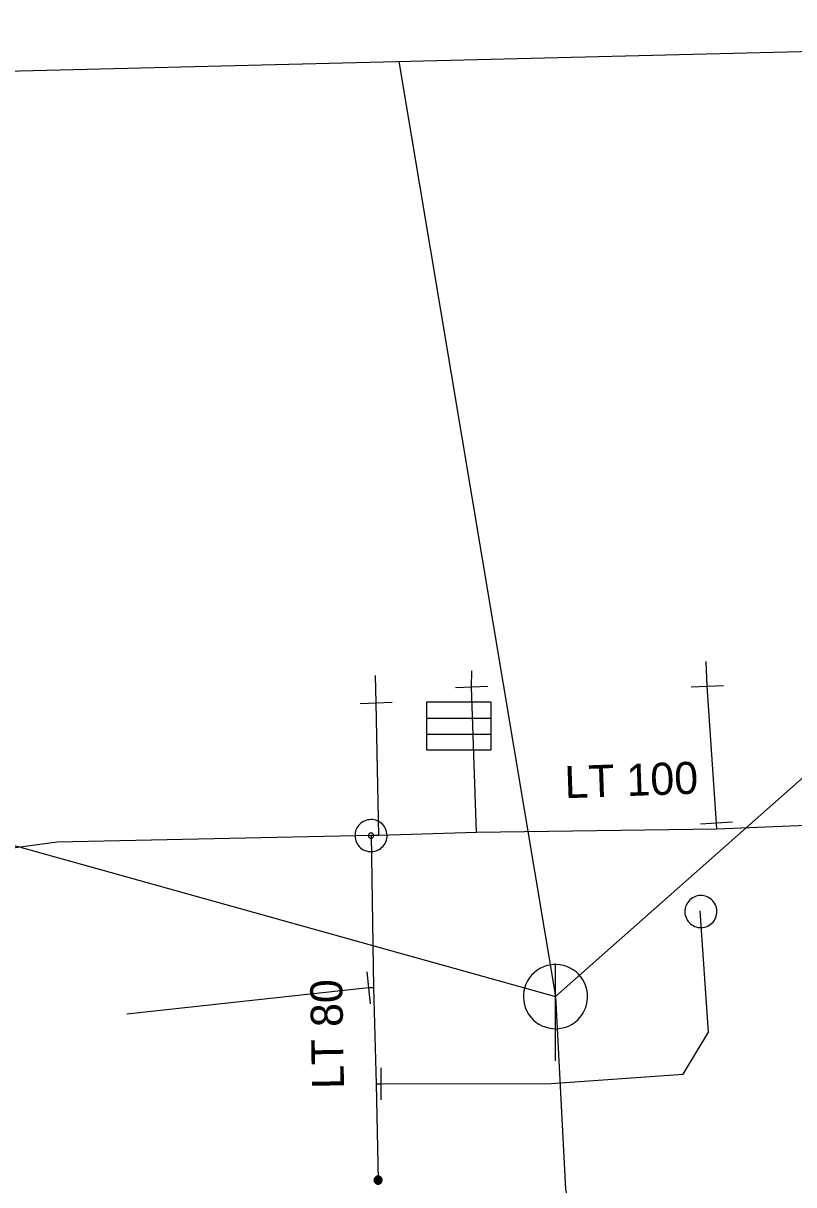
# Model space of a CAD drawing. Extents: x -725807 to -725723.1, y -978165.9 to -978101.2.
# Drawn here: x -725783 to -725758.99, y -978137.33 to -978101.16 of the extents above; entities that cross this region are included whole.
import ezdxf

# ---------------------------------------------------------------- set-up
doc = ezdxf.new("R2010")
doc.units = 0
for name, color, linetype in [('Vrstva 1', 7, 'Continuous'), ('Vrstva 13', 7, 'Continuous'), ('Vrstva 14', 7, 'Continuous'), ('Vrstva 17', 7, 'Continuous'), ('Vrstva 22', 7, 'Continuous'), ('Vrstva 23', 7, 'Continuous'), ('Vrstva 34', 7, 'Continuous'), ('Vrstva 47', 7, 'Continuous'), ('Vrstva 9', 7, 'Continuous')]:
    doc.layers.add(name, color=color, linetype=linetype)

msp = doc.modelspace()

# ---------------------------------------------------------------- linework, layer by layer
at = {"layer": 'Vrstva 1'}
msp.add_lwpolyline([(-725807.01, -978138.838), (-725796.543, -978102.971), (-725723.134, -978101.157), (-725729.135, -978159.354), (-725758.583, -978165.913), (-725792.915, -978158.237)], close=True, dxfattribs=at)
at = {"layer": 'Vrstva 13'}
for points in [[(-725761.689, -978121.798), (-725761.728, -978121.035)], [(-725772.006, -978122.318), (-725772.024, -978121.471)], [(-725769.031, -978121.822), (-725769.026, -978121.326)], [(-725768.881, -978126.353), (-725769.031, -978121.822)], [(-725761.4, -978126.068), (-725761.689, -978121.798)], [(-725771.927, -978126.449), (-725772.006, -978122.318)], [(-725771.861, -978134.181), (-725766.555, -978134.175), (-725762.44, -978133.877), (-725761.649, -978132.576), (-725761.907, -978128.792)], [(-725772.245, -978131.191), (-725779.778, -978132.017)]]:
    msp.add_lwpolyline(points, dxfattribs=at)
at = {"layer": 'Vrstva 14'}
for points in [[(-725771.298, -978102.347), (-725766.42, -978131.467)], [(-725801.965, -978121.55), (-725766.42, -978131.467)], [(-725750.922, -978123.543), (-725758.582, -978124.535), (-725766.42, -978131.467)], [(-725761.388, -978126.258), (-725761.4, -978126.068)], [(-725772.085, -978131.19), (-725772.245, -978131.191)], [(-725766.42, -978131.467), (-725766.103, -978137.458), (-725764.695, -978144.424), (-725761.772, -978159.113), (-725761.702, -978159.462), (-725760.504, -978165.484)], [(-725772.01, -978134.181), (-725771.861, -978134.181)]]:
    msp.add_lwpolyline(points, dxfattribs=at)
at = {"layer": 'Vrstva 17'}
for points in [[(-725754.02, -978125.954), (-725761.388, -978126.258), (-725768.881, -978126.353), (-725771.927, -978126.449), (-725772.166, -978126.454)], [(-725772.166, -978126.454), (-725781.945, -978126.655), (-725795.783, -978128.538)], [(-725772.166, -978126.454), (-725772.085, -978131.19), (-725772.01, -978134.181), (-725771.946, -978137.181)]]:
    msp.add_lwpolyline(points, dxfattribs=at)
at = {"layer": 'Vrstva 22'}
for points in [[(-725770.431, -978122.293), (-725768.431, -978122.293), (-725768.431, -978123.793), (-725770.431, -978123.793), (-725770.431, -978122.293)], [(-725770.431, -978122.793), (-725768.431, -978122.793)], [(-725770.431, -978123.293), (-725768.431, -978123.293)], [(-725765.42, -978131.467), (-725765.425, -978131.358), (-725765.443, -978131.25), (-725765.473, -978131.144), (-725765.513, -978131.043), (-725765.565, -978130.946), (-725765.627, -978130.856), (-725765.699, -978130.773), (-725765.779, -978130.699), (-725765.867, -978130.633), (-725765.961, -978130.578), (-725766.061, -978130.533), (-725766.166, -978130.5), (-725766.273, -978130.478), (-725766.382, -978130.468), (-725766.492, -978130.47), (-725766.6, -978130.484), (-725766.707, -978130.509), (-725766.81, -978130.546), (-725766.908, -978130.595), (-725767, -978130.653), (-725767.086, -978130.722), (-725767.163, -978130.799), (-725767.232, -978130.885), (-725767.291, -978130.977), (-725767.339, -978131.075), (-725767.376, -978131.178), (-725767.402, -978131.285), (-725767.416, -978131.393), (-725767.419, -978131.503), (-725767.409, -978131.612), (-725767.388, -978131.719), (-725767.354, -978131.823), (-725767.31, -978131.923), (-725767.255, -978132.018), (-725767.189, -978132.106), (-725767.115, -978132.186), (-725767.032, -978132.258), (-725766.942, -978132.32), (-725766.846, -978132.372), (-725766.744, -978132.413), (-725766.639, -978132.443), (-725766.531, -978132.461), (-725766.421, -978132.467), (-725766.312, -978132.461), (-725766.204, -978132.443), (-725766.099, -978132.414), (-725765.997, -978132.373), (-725765.9, -978132.321), (-725765.81, -978132.259), (-725765.727, -978132.188), (-725765.652, -978132.108), (-725765.587, -978132.02), (-725765.531, -978131.926), (-725765.487, -978131.826), (-725765.453, -978131.722), (-725765.431, -978131.614), (-725765.421, -978131.505), (-725765.42, -978131.467)], [(-725766.42, -978133.467), (-725766.419, -978130.467)]]:
    msp.add_lwpolyline(points, dxfattribs=at)
at = {"layer": 'Vrstva 23'}
for points in [[(-725762.148, -978128.392), (-725762.191, -978128.422)], [(-725762.148, -978128.392), (-725762.191, -978128.422)], [(-725762.103, -978128.368), (-725762.148, -978128.392)], [(-725762.103, -978128.368), (-725762.148, -978128.392)], [(-725762.054, -978128.347), (-725762.103, -978128.368)], [(-725762.054, -978128.347), (-725762.103, -978128.368)], [(-725762.004, -978128.332), (-725762.054, -978128.347)], [(-725762.004, -978128.332), (-725762.054, -978128.347)], [(-725761.952, -978128.323), (-725762.004, -978128.332)], [(-725761.952, -978128.323), (-725762.004, -978128.332)], [(-725761.901, -978128.318), (-725761.952, -978128.323)], [(-725761.901, -978128.318), (-725761.952, -978128.323)], [(-725761.848, -978128.32), (-725761.901, -978128.318)], [(-725761.848, -978128.32), (-725761.901, -978128.318)], [(-725761.796, -978128.327), (-725761.848, -978128.32)], [(-725761.796, -978128.327), (-725761.848, -978128.32)], [(-725761.745, -978128.34), (-725761.796, -978128.327)], [(-725761.745, -978128.34), (-725761.796, -978128.327)], [(-725761.697, -978128.358), (-725761.745, -978128.34)], [(-725761.697, -978128.358), (-725761.745, -978128.34)], [(-725761.649, -978128.38), (-725761.697, -978128.358)], [(-725761.649, -978128.38), (-725761.697, -978128.358)], [(-725761.605, -978128.407), (-725761.649, -978128.38)], [(-725761.605, -978128.407), (-725761.649, -978128.38)], [(-725762.38, -978128.725), (-725762.387, -978128.779)], [(-725762.38, -978128.725), (-725762.387, -978128.779)], [(-725762.367, -978128.675), (-725762.38, -978128.725)], [(-725762.367, -978128.675), (-725762.38, -978128.725)], [(-725762.35, -978128.626), (-725762.367, -978128.675)], [(-725762.35, -978128.626), (-725762.367, -978128.675)], [(-725762.328, -978128.58), (-725762.35, -978128.626)], [(-725762.328, -978128.58), (-725762.35, -978128.626)], [(-725762.3, -978128.534), (-725762.328, -978128.58)], [(-725762.3, -978128.534), (-725762.328, -978128.58)], [(-725762.267, -978128.493), (-725762.3, -978128.534)], [(-725762.267, -978128.493), (-725762.3, -978128.534)], [(-725762.231, -978128.455), (-725762.267, -978128.493)], [(-725762.231, -978128.455), (-725762.267, -978128.493)], [(-725762.191, -978128.422), (-725762.231, -978128.455)], [(-725762.191, -978128.422), (-725762.231, -978128.455)], [(-725761.563, -978128.439), (-725761.605, -978128.407)], [(-725761.563, -978128.439), (-725761.605, -978128.407)], [(-725761.525, -978128.476), (-725761.563, -978128.439)], [(-725761.525, -978128.476), (-725761.563, -978128.439)], [(-725761.491, -978128.516), (-725761.525, -978128.476)], [(-725761.491, -978128.516), (-725761.525, -978128.476)], [(-725761.463, -978128.559), (-725761.491, -978128.516)], [(-725761.463, -978128.559), (-725761.491, -978128.516)], [(-725761.436, -978128.605), (-725761.463, -978128.559)], [(-725761.436, -978128.605), (-725761.463, -978128.559)], [(-725761.417, -978128.653), (-725761.436, -978128.605)], [(-725761.417, -978128.653), (-725761.436, -978128.605)], [(-725761.403, -978128.704), (-725761.417, -978128.653)], [(-725761.403, -978128.704), (-725761.417, -978128.653)], [(-725761.393, -978128.755), (-725761.403, -978128.704)], [(-725761.393, -978128.755), (-725761.403, -978128.704)], [(-725761.389, -978128.807), (-725761.393, -978128.755)], [(-725761.389, -978128.807), (-725761.393, -978128.755)], [(-725762.387, -978128.779), (-725762.389, -978128.83)], [(-725762.387, -978128.779), (-725762.389, -978128.83)], [(-725762.389, -978128.83), (-725762.384, -978128.884)], [(-725762.389, -978128.83), (-725762.384, -978128.884)], [(-725762.384, -978128.884), (-725762.376, -978128.933)], [(-725762.384, -978128.884), (-725762.376, -978128.933)], [(-725762.376, -978128.933), (-725762.362, -978128.984)], [(-725762.376, -978128.933), (-725762.362, -978128.984)], [(-725762.362, -978128.984), (-725762.34, -978129.033)], [(-725762.362, -978128.984), (-725762.34, -978129.033)], [(-725762.34, -978129.033), (-725762.315, -978129.079)], [(-725762.34, -978129.033), (-725762.315, -978129.079)], [(-725762.315, -978129.079), (-725762.285, -978129.123)], [(-725762.315, -978129.079), (-725762.285, -978129.123)], [(-725761.51, -978129.145), (-725761.478, -978129.103)], [(-725761.51, -978129.145), (-725761.478, -978129.103)], [(-725761.478, -978129.103), (-725761.45, -978129.059)], [(-725761.478, -978129.103), (-725761.45, -978129.059)], [(-725761.45, -978129.059), (-725761.428, -978129.011)], [(-725761.45, -978129.059), (-725761.428, -978129.011)], [(-725761.428, -978129.011), (-725761.411, -978128.962)], [(-725761.428, -978129.011), (-725761.411, -978128.962)], [(-725761.411, -978128.962), (-725761.398, -978128.912)], [(-725761.411, -978128.962), (-725761.398, -978128.912)], [(-725761.398, -978128.912), (-725761.391, -978128.86)], [(-725761.398, -978128.912), (-725761.391, -978128.86)], [(-725761.391, -978128.86), (-725761.389, -978128.807)], [(-725761.391, -978128.86), (-725761.389, -978128.807)], [(-725762.285, -978129.123), (-725762.253, -978129.163)], [(-725762.285, -978129.123), (-725762.253, -978129.163)], [(-725762.253, -978129.163), (-725762.215, -978129.198)], [(-725762.253, -978129.163), (-725762.215, -978129.198)], [(-725762.215, -978129.198), (-725762.172, -978129.23)], [(-725762.215, -978129.198), (-725762.172, -978129.23)], [(-725762.172, -978129.23), (-725762.129, -978129.257)], [(-725762.172, -978129.23), (-725762.129, -978129.257)], [(-725762.129, -978129.257), (-725762.081, -978129.28)], [(-725762.129, -978129.257), (-725762.081, -978129.28)], [(-725762.081, -978129.28), (-725762.032, -978129.297)], [(-725762.081, -978129.28), (-725762.032, -978129.297)], [(-725762.032, -978129.297), (-725761.981, -978129.31)], [(-725762.032, -978129.297), (-725761.981, -978129.31)], [(-725761.981, -978129.31), (-725761.93, -978129.317)], [(-725761.981, -978129.31), (-725761.93, -978129.317)], [(-725761.93, -978129.317), (-725761.877, -978129.319)], [(-725761.93, -978129.317), (-725761.877, -978129.319)], [(-725761.877, -978129.319), (-725761.824, -978129.315)], [(-725761.877, -978129.319), (-725761.824, -978129.315)], [(-725761.824, -978129.315), (-725761.773, -978129.306)], [(-725761.824, -978129.315), (-725761.773, -978129.306)], [(-725761.773, -978129.306), (-725761.724, -978129.29)], [(-725761.773, -978129.306), (-725761.724, -978129.29)], [(-725761.724, -978129.29), (-725761.675, -978129.27)], [(-725761.724, -978129.29), (-725761.675, -978129.27)], [(-725761.675, -978129.27), (-725761.629, -978129.246)], [(-725761.675, -978129.27), (-725761.629, -978129.246)], [(-725761.629, -978129.246), (-725761.585, -978129.216)], [(-725761.629, -978129.246), (-725761.585, -978129.216)], [(-725761.585, -978129.216), (-725761.546, -978129.182)], [(-725761.585, -978129.216), (-725761.546, -978129.182)], [(-725761.546, -978129.182), (-725761.51, -978129.145)], [(-725761.546, -978129.182), (-725761.51, -978129.145)]]:
    msp.add_lwpolyline(points, dxfattribs=at)
at = {"layer": 'Vrstva 34'}
for points in [[(-725769.53, -978121.841), (-725768.531, -978121.803)], [(-725762.188, -978121.817), (-725761.189, -978121.779)], [(-725772.505, -978122.337), (-725771.506, -978122.299)], [(-725760.901, -978126.033), (-725761.898, -978126.101)], [(-725772.299, -978130.694), (-725772.19, -978131.688)], [(-725771.858, -978133.681), (-725771.864, -978134.68)]]:
    msp.add_lwpolyline(points, dxfattribs=at)
at = {"layer": 'Vrstva 47'}
for points in [[(-725772.155, -978126.953), (-725772.103, -978126.949), (-725772.051, -978126.94), (-725772.002, -978126.925), (-725771.953, -978126.906), (-725771.907, -978126.881), (-725771.863, -978126.851), (-725771.824, -978126.818), (-725771.788, -978126.78), (-725771.756, -978126.739), (-725771.727, -978126.695), (-725771.704, -978126.647), (-725771.687, -978126.598), (-725771.674, -978126.547), (-725771.668, -978126.495), (-725771.666, -978126.443), (-725771.67, -978126.391), (-725771.679, -978126.339), (-725771.694, -978126.289), (-725771.713, -978126.241), (-725771.738, -978126.195), (-725771.768, -978126.151), (-725771.801, -978126.111), (-725771.839, -978126.075), (-725771.88, -978126.043), (-725771.924, -978126.015), (-725771.972, -978125.992), (-725772.021, -978125.974), (-725772.072, -978125.962), (-725772.124, -978125.956), (-725772.176, -978125.954), (-725772.228, -978125.958), (-725772.28, -978125.967), (-725772.33, -978125.981), (-725772.378, -978126.001), (-725772.424, -978126.026), (-725772.468, -978126.055), (-725772.508, -978126.088), (-725772.544, -978126.126), (-725772.576, -978126.168), (-725772.604, -978126.212), (-725772.627, -978126.26), (-725772.645, -978126.308), (-725772.657, -978126.36), (-725772.663, -978126.412), (-725772.665, -978126.464), (-725772.661, -978126.516), (-725772.652, -978126.568), (-725772.638, -978126.617), (-725772.618, -978126.666), (-725772.593, -978126.712), (-725772.564, -978126.756), (-725772.531, -978126.795), (-725772.493, -978126.831), (-725772.451, -978126.863), (-725772.407, -978126.892), (-725772.359, -978126.915), (-725772.311, -978126.932), (-725772.259, -978126.945), (-725772.207, -978126.951), (-725772.155, -978126.953)], [(-725772.164, -978126.535), (-725772.155, -978126.535), (-725772.147, -978126.533), (-725772.139, -978126.531), (-725772.131, -978126.528), (-725772.123, -978126.524), (-725772.116, -978126.519), (-725772.109, -978126.513), (-725772.103, -978126.507), (-725772.099, -978126.5), (-725772.094, -978126.493), (-725772.09, -978126.485), (-725772.087, -978126.477), (-725772.085, -978126.469), (-725772.083, -978126.461), (-725772.084, -978126.452), (-725772.084, -978126.443), (-725772.086, -978126.435), (-725772.088, -978126.427), (-725772.091, -978126.419), (-725772.095, -978126.411), (-725772.1, -978126.404), (-725772.106, -978126.397), (-725772.112, -978126.391), (-725772.119, -978126.386), (-725772.126, -978126.382), (-725772.134, -978126.378), (-725772.142, -978126.375), (-725772.15, -978126.373), (-725772.158, -978126.371), (-725772.167, -978126.372), (-725772.176, -978126.372), (-725772.184, -978126.374), (-725772.192, -978126.376), (-725772.2, -978126.379), (-725772.208, -978126.383), (-725772.215, -978126.387), (-725772.222, -978126.394), (-725772.228, -978126.4), (-725772.233, -978126.407), (-725772.237, -978126.414), (-725772.241, -978126.422), (-725772.244, -978126.43), (-725772.246, -978126.438), (-725772.248, -978126.446), (-725772.247, -978126.455), (-725772.247, -978126.464), (-725772.245, -978126.472), (-725772.243, -978126.48), (-725772.24, -978126.488), (-725772.236, -978126.496), (-725772.232, -978126.503), (-725772.225, -978126.51), (-725772.219, -978126.516), (-725772.212, -978126.52), (-725772.205, -978126.525), (-725772.197, -978126.529), (-725772.189, -978126.532), (-725772.181, -978126.534), (-725772.173, -978126.536), (-725772.164, -978126.535)]]:
    msp.add_lwpolyline(points, dxfattribs=at)
at = {"layer": 'Vrstva 9'}
for points in [[(-725772.072, -978137.181), (-725772.072, -978137.194), (-725772.07, -978137.207), (-725772.067, -978137.22), (-725772.062, -978137.232), (-725772.056, -978137.244), (-725772.049, -978137.255), (-725772.041, -978137.265), (-725772.031, -978137.275), (-725772.021, -978137.283), (-725772.01, -978137.29), (-725771.998, -978137.296), (-725771.986, -978137.301), (-725771.973, -978137.304), (-725771.96, -978137.306), (-725771.947, -978137.308), (-725771.934, -978137.307), (-725771.921, -978137.305), (-725771.908, -978137.302), (-725771.896, -978137.297), (-725771.884, -978137.291), (-725771.873, -978137.284), (-725771.863, -978137.276), (-725771.853, -978137.266), (-725771.845, -978137.256), (-725771.838, -978137.245), (-725771.832, -978137.233), (-725771.827, -978137.221), (-725771.824, -978137.208), (-725771.822, -978137.195), (-725771.82, -978137.182), (-725771.821, -978137.169), (-725771.823, -978137.156), (-725771.826, -978137.143), (-725771.831, -978137.131), (-725771.837, -978137.119), (-725771.844, -978137.108), (-725771.852, -978137.098), (-725771.862, -978137.088), (-725771.872, -978137.08), (-725771.883, -978137.073), (-725771.895, -978137.067), (-725771.907, -978137.062), (-725771.92, -978137.059), (-725771.933, -978137.057), (-725771.946, -978137.056), (-725771.959, -978137.056), (-725771.972, -978137.058), (-725771.985, -978137.061), (-725771.997, -978137.066), (-725772.009, -978137.072), (-725772.02, -978137.079), (-725772.03, -978137.087), (-725772.04, -978137.097), (-725772.048, -978137.107), (-725772.055, -978137.118), (-725772.061, -978137.13), (-725772.066, -978137.142), (-725772.069, -978137.155), (-725772.071, -978137.168), (-725772.072, -978137.181)], [(-725772.052, -978137.181), (-725772.053, -978137.192), (-725772.051, -978137.203), (-725772.048, -978137.214), (-725772.044, -978137.224), (-725772.039, -978137.234), (-725772.033, -978137.243), (-725772.026, -978137.252), (-725772.018, -978137.26), (-725772.009, -978137.267), (-725772, -978137.273), (-725771.99, -978137.278), (-725771.98, -978137.282), (-725771.969, -978137.285), (-725771.958, -978137.288), (-725771.947, -978137.288), (-725771.936, -978137.288), (-725771.925, -978137.286), (-725771.914, -978137.283), (-725771.904, -978137.279), (-725771.894, -978137.274), (-725771.885, -978137.268), (-725771.876, -978137.261), (-725771.868, -978137.253), (-725771.861, -978137.244), (-725771.855, -978137.235), (-725771.85, -978137.225), (-725771.846, -978137.215), (-725771.843, -978137.204), (-725771.841, -978137.193), (-725771.84, -978137.182), (-725771.84, -978137.171), (-725771.842, -978137.16), (-725771.845, -978137.149), (-725771.849, -978137.139), (-725771.854, -978137.129), (-725771.86, -978137.12), (-725771.867, -978137.111), (-725771.875, -978137.103), (-725771.884, -978137.096), (-725771.893, -978137.09), (-725771.903, -978137.085), (-725771.913, -978137.081), (-725771.924, -978137.078), (-725771.934, -978137.076), (-725771.946, -978137.076), (-725771.957, -978137.075), (-725771.968, -978137.077), (-725771.979, -978137.08), (-725771.989, -978137.084), (-725771.999, -978137.089), (-725772.008, -978137.095), (-725772.017, -978137.102), (-725772.025, -978137.11), (-725772.032, -978137.119), (-725772.038, -978137.128), (-725772.043, -978137.138), (-725772.047, -978137.148), (-725772.05, -978137.159), (-725772.052, -978137.17), (-725772.052, -978137.181)], [(-725772.033, -978137.181), (-725772.033, -978137.19), (-725772.032, -978137.199), (-725772.029, -978137.208), (-725772.026, -978137.216), (-725772.022, -978137.224), (-725772.017, -978137.232), (-725772.011, -978137.239), (-725772.005, -978137.245), (-725771.998, -978137.251), (-725771.99, -978137.256), (-725771.982, -978137.26), (-725771.974, -978137.263), (-725771.965, -978137.266), (-725771.956, -978137.267), (-725771.947, -978137.269), (-725771.938, -978137.268), (-725771.929, -978137.267), (-725771.92, -978137.264), (-725771.912, -978137.261), (-725771.904, -978137.257), (-725771.896, -978137.252), (-725771.889, -978137.246), (-725771.883, -978137.24), (-725771.877, -978137.233), (-725771.872, -978137.225), (-725771.868, -978137.217), (-725771.865, -978137.209), (-725771.862, -978137.2), (-725771.861, -978137.191), (-725771.858, -978137.182), (-725771.86, -978137.173), (-725771.861, -978137.164), (-725771.864, -978137.155), (-725771.867, -978137.147), (-725771.871, -978137.139), (-725771.876, -978137.131), (-725771.882, -978137.124), (-725771.888, -978137.118), (-725771.895, -978137.112), (-725771.903, -978137.107), (-725771.911, -978137.103), (-725771.919, -978137.1), (-725771.928, -978137.097), (-725771.937, -978137.096), (-725771.946, -978137.095), (-725771.955, -978137.095), (-725771.964, -978137.096), (-725771.973, -978137.099), (-725771.981, -978137.102), (-725771.989, -978137.106), (-725771.997, -978137.111), (-725772.004, -978137.117), (-725772.01, -978137.123), (-725772.016, -978137.13), (-725772.021, -978137.138), (-725772.025, -978137.146), (-725772.028, -978137.154), (-725772.031, -978137.163), (-725772.032, -978137.172), (-725772.033, -978137.181)], [(-725772.013, -978137.181), (-725772.013, -978137.188), (-725772.012, -978137.195), (-725772.011, -978137.202), (-725772.008, -978137.208), (-725772.005, -978137.214), (-725772.001, -978137.22), (-725771.997, -978137.226), (-725771.992, -978137.231), (-725771.986, -978137.235), (-725771.98, -978137.239), (-725771.974, -978137.242), (-725771.968, -978137.245), (-725771.961, -978137.246), (-725771.954, -978137.249), (-725771.947, -978137.249), (-725771.94, -978137.249), (-725771.933, -978137.247), (-725771.926, -978137.246), (-725771.92, -978137.243), (-725771.913, -978137.24), (-725771.908, -978137.236), (-725771.902, -978137.232), (-725771.897, -978137.227), (-725771.893, -978137.221), (-725771.889, -978137.215), (-725771.886, -978137.209), (-725771.883, -978137.203), (-725771.881, -978137.196), (-725771.88, -978137.189), (-725771.879, -978137.182), (-725771.879, -978137.175), (-725771.88, -978137.168), (-725771.882, -978137.161), (-725771.885, -978137.155), (-725771.888, -978137.148), (-725771.892, -978137.143), (-725771.896, -978137.137), (-725771.901, -978137.132), (-725771.907, -978137.128), (-725771.912, -978137.124), (-725771.919, -978137.121), (-725771.925, -978137.118), (-725771.932, -978137.116), (-725771.939, -978137.115), (-725771.946, -978137.115), (-725771.953, -978137.115), (-725771.96, -978137.115), (-725771.967, -978137.117), (-725771.973, -978137.12), (-725771.979, -978137.123), (-725771.985, -978137.127), (-725771.991, -978137.131), (-725771.996, -978137.136), (-725772, -978137.142), (-725772.004, -978137.147), (-725772.007, -978137.154), (-725772.01, -978137.16), (-725772.011, -978137.167), (-725772.013, -978137.174), (-725772.013, -978137.181)], [(-725771.993, -978137.181), (-725771.993, -978137.186), (-725771.993, -978137.191), (-725771.992, -978137.196), (-725771.99, -978137.2), (-725771.988, -978137.205), (-725771.985, -978137.209), (-725771.982, -978137.212), (-725771.978, -978137.216), (-725771.975, -978137.219), (-725771.971, -978137.222), (-725771.966, -978137.224), (-725771.962, -978137.226), (-725771.957, -978137.227), (-725771.952, -978137.229), (-725771.947, -978137.229), (-725771.942, -978137.229), (-725771.937, -978137.228), (-725771.932, -978137.227), (-725771.928, -978137.225), (-725771.923, -978137.223), (-725771.919, -978137.22), (-725771.915, -978137.217), (-725771.912, -978137.213), (-725771.909, -978137.21), (-725771.906, -978137.206), (-725771.904, -978137.201), (-725771.902, -978137.197), (-725771.901, -978137.192), (-725771.9, -978137.187), (-725771.899, -978137.182), (-725771.899, -978137.177), (-725771.9, -978137.172), (-725771.901, -978137.167), (-725771.903, -978137.163), (-725771.905, -978137.158), (-725771.908, -978137.154), (-725771.911, -978137.15), (-725771.914, -978137.147), (-725771.918, -978137.144), (-725771.922, -978137.141), (-725771.927, -978137.139), (-725771.931, -978137.137), (-725771.936, -978137.136), (-725771.941, -978137.135), (-725771.946, -978137.135), (-725771.951, -978137.135), (-725771.956, -978137.136), (-725771.961, -978137.136), (-725771.965, -978137.138), (-725771.97, -978137.14), (-725771.974, -978137.143), (-725771.977, -978137.146), (-725771.981, -978137.149), (-725771.983, -978137.153), (-725771.987, -978137.157), (-725771.989, -978137.162), (-725771.991, -978137.166), (-725771.992, -978137.171), (-725771.993, -978137.176), (-725771.993, -978137.181)], [(-725771.973, -978137.181), (-725771.973, -978137.184), (-725771.974, -978137.187), (-725771.973, -978137.189), (-725771.972, -978137.192), (-725771.971, -978137.195), (-725771.969, -978137.197), (-725771.967, -978137.199), (-725771.965, -978137.201), (-725771.963, -978137.203), (-725771.961, -978137.205), (-725771.958, -978137.207), (-725771.955, -978137.208), (-725771.953, -978137.208), (-725771.95, -978137.209), (-725771.947, -978137.209), (-725771.944, -978137.209), (-725771.941, -978137.209), (-725771.938, -978137.208), (-725771.936, -978137.207), (-725771.933, -978137.206), (-725771.931, -978137.204), (-725771.928, -978137.202), (-725771.926, -978137.2), (-725771.925, -978137.198), (-725771.923, -978137.196), (-725771.922, -978137.193), (-725771.92, -978137.19), (-725771.92, -978137.188), (-725771.919, -978137.185), (-725771.918, -978137.182), (-725771.919, -978137.179), (-725771.919, -978137.176), (-725771.92, -978137.173), (-725771.921, -978137.171), (-725771.922, -978137.168), (-725771.924, -978137.166), (-725771.925, -978137.163), (-725771.927, -978137.161), (-725771.93, -978137.16), (-725771.932, -978137.158), (-725771.934, -978137.157), (-725771.937, -978137.156), (-725771.94, -978137.155), (-725771.943, -978137.155), (-725771.946, -978137.154), (-725771.949, -978137.155), (-725771.952, -978137.154), (-725771.954, -978137.156), (-725771.957, -978137.156), (-725771.96, -978137.157), (-725771.962, -978137.159), (-725771.964, -978137.16), (-725771.966, -978137.162), (-725771.968, -978137.165), (-725771.97, -978137.167), (-725771.971, -978137.17), (-725771.972, -978137.172), (-725771.973, -978137.175), (-725771.973, -978137.178), (-725771.973, -978137.181)], [(-725771.954, -978137.181), (-725771.954, -978137.183), (-725771.954, -978137.183), (-725771.953, -978137.183), (-725771.953, -978137.185), (-725771.954, -978137.186), (-725771.952, -978137.186), (-725771.952, -978137.186), (-725771.952, -978137.188), (-725771.952, -978137.188), (-725771.951, -978137.189), (-725771.949, -978137.189), (-725771.949, -978137.189), (-725771.949, -978137.19), (-725771.947, -978137.19), (-725771.947, -978137.19), (-725771.946, -978137.19), (-725771.945, -978137.19), (-725771.945, -978137.189), (-725771.944, -978137.189), (-725771.942, -978137.189), (-725771.942, -978137.188), (-725771.942, -978137.188), (-725771.941, -978137.187), (-725771.941, -978137.187), (-725771.939, -978137.186), (-725771.939, -978137.185), (-725771.938, -978137.184), (-725771.938, -978137.184), (-725771.938, -978137.183), (-725771.938, -978137.182), (-725771.938, -978137.181), (-725771.938, -978137.18), (-725771.938, -978137.18), (-725771.939, -978137.179), (-725771.939, -978137.178), (-725771.94, -978137.177), (-725771.94, -978137.177), (-725771.941, -978137.176), (-725771.941, -978137.176), (-725771.942, -978137.175), (-725771.943, -978137.175), (-725771.944, -978137.174), (-725771.944, -978137.174), (-725771.945, -978137.174), (-725771.946, -978137.174), (-725771.947, -978137.174), (-725771.948, -978137.174), (-725771.948, -978137.174), (-725771.949, -978137.175), (-725771.95, -978137.174), (-725771.951, -978137.176), (-725771.951, -978137.176), (-725771.952, -978137.176), (-725771.952, -978137.176), (-725771.953, -978137.178), (-725771.953, -978137.179), (-725771.953, -978137.18), (-725771.954, -978137.18), (-725771.954, -978137.181), (-725771.954, -978137.181)]]:
    msp.add_lwpolyline(points, dxfattribs=at)

# ---------------------------------------------------------------- texts
at = {"layer": 'Vrstva 1'}
for s, rotation, p in [('LT 100', 2, (-725766.12, -978125.291)), ('LT 80 ', 91, (-725773.005, -978134.337))]:
    msp.add_text(s, height=1, rotation=rotation, dxfattribs=at).set_placement(p)

doc.saveas('drawing.dxf')
